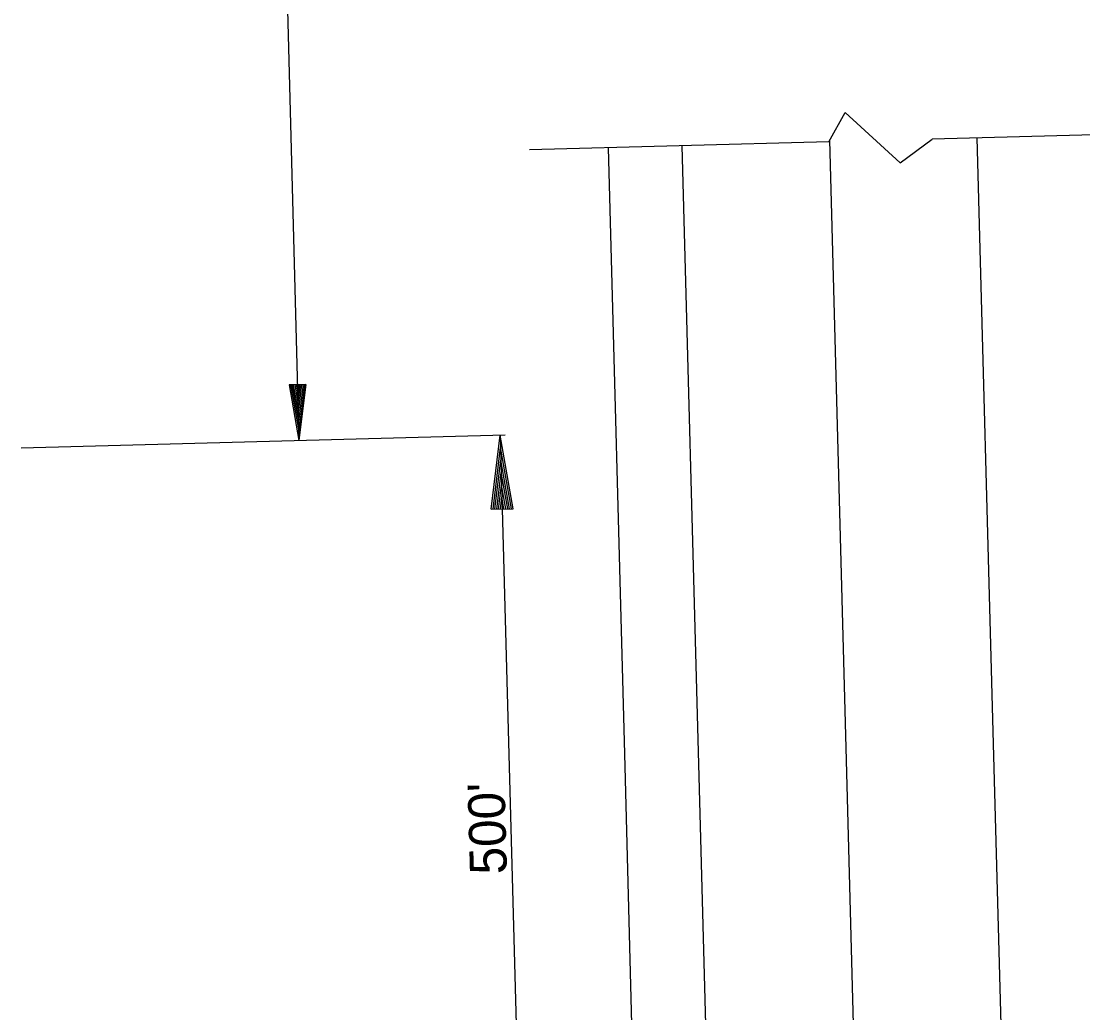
# Model space of a CAD drawing. Extents: x 1929653 to 1931621, y 596452 to 600944.
# Drawn here: x 1930720.5 to 1930892.7, y 600063.8 to 600224.5 of the extents above; entities that cross this region are included whole.
import ezdxf

# ---------------------------------------------------------------- set-up
doc = ezdxf.new("R2010")
doc.units = 0
doc.layers.add('R_Draft', color=7, linetype='Continuous')

msp = doc.modelspace()

# ---------------------------------------------------------------- linework, layer by layer
at = {"layer": 'R_Draft'}
for p, q in [((1930757.32, 600464.55), (1930765.59, 600156.53)), ((1930902.74, 600206.32), (1930868.3, 600205.4)), ((1930851.53, 600204.95), (1930802.96, 600203.65)), ((1930818.42, 600105.78), (1930815.79, 600203.99)), ((1930830.39, 600106.1), (1930827.75, 600204.31)), ((1930854.32, 600106.75), (1930851.67, 600205.21)), ((1930878.25, 600107.39), (1930875.61, 600205.6)), ((1930766.7, 600165.63), (1930763.98, 600165.56)), ((1930763.98, 600165.56), (1930765.59, 600156.53)), ((1930764.21, 600165.57), (1930765.55, 600158.05)), ((1930764.44, 600165.57), (1930765.5, 600159.61)), ((1930764.67, 600165.58), (1930765.46, 600161.12)), ((1930764.9, 600165.59), (1930765.42, 600162.65)), ((1930765.13, 600165.59), (1930765.38, 600164.17)), ((1930765.56, 600165.6), (1930765.38, 600164.17)), ((1930765.78, 600165.61), (1930765.42, 600162.65)), ((1930766.02, 600165.62), (1930765.46, 600161.12)), ((1930766.25, 600165.62), (1930765.5, 600159.61)), ((1930766.48, 600165.63), (1930765.55, 600158.05)), ((1930766.7, 600165.63), (1930765.59, 600156.53)), ((1930799.04, 600157.43), (1930720.54, 600155.32)), ((1930796.77, 600145.4), (1930798.24, 600157.41)), ((1930798.24, 600157.41), (1930801.52, 600035.08)), ((1930800.36, 600145.49), (1930798.24, 600157.41)), ((1930797.07, 600145.4), (1930798.29, 600155.41)), ((1930800.06, 600145.49), (1930798.29, 600155.41)), ((1930797.37, 600145.41), (1930798.35, 600153.35)), ((1930799.75, 600145.48), (1930798.35, 600153.35)), ((1930797.67, 600145.42), (1930798.4, 600151.36)), ((1930799.45, 600145.47), (1930798.4, 600151.36)), ((1930797.98, 600145.43), (1930798.46, 600149.33)), ((1930799.15, 600145.46), (1930798.46, 600149.33)), ((1930798.28, 600145.44), (1930798.51, 600147.34)), ((1930798.84, 600145.45), (1930798.51, 600147.34)), ((1930796.77, 600145.4), (1930800.36, 600145.49)), ((1930842.03, 599672.25), (1930830.39, 600106.1)), ((1930865.96, 599672.89), (1930854.32, 600106.75)), ((1930889.89, 599673.54), (1930878.25, 600107.39)), ((1930830.07, 599671.93), (1930818.42, 600105.78))]:
    msp.add_line(p, q, dxfattribs=at)
msp.add_lwpolyline([(1930851.53, 600204.95), (1930854.21, 600209.74), (1930863.13, 600201.55), (1930868.3, 600205.4)], dxfattribs=at)

# ---------------------------------------------------------------- texts
msp.add_text("500'", height=6, rotation=91.5377, dxfattribs=at).set_placement((1930799.33, 600086.28))

doc.saveas('drawing.dxf')
